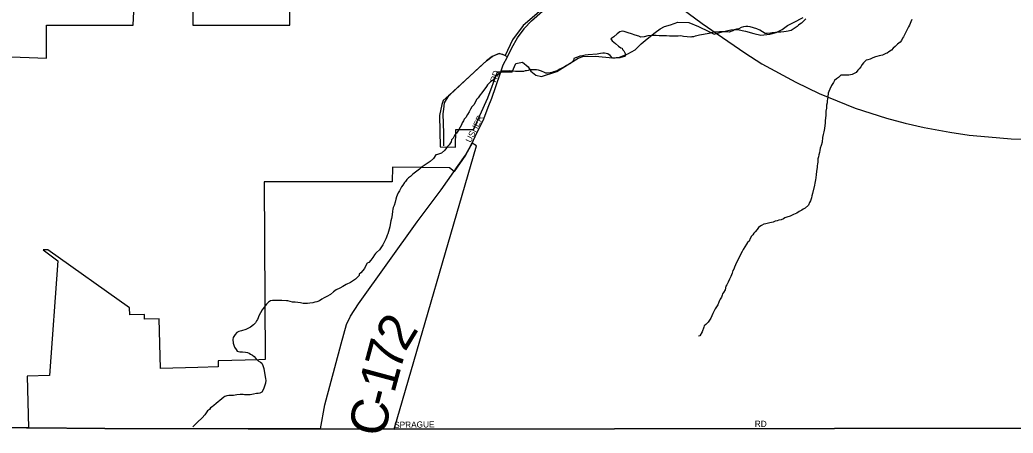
# Model space of a CAD drawing. Extents: x 2010165 to 2382125, y 1060529 to 1407316.
# Drawn here: x 2123534 to 2131582, y 1221198 to 1224542 of the extents above; entities that cross this region are included whole.
import ezdxf

# ---------------------------------------------------------------- set-up
doc = ezdxf.new("R2010")
doc.units = 0
for name, color, linetype in [('GM_X_Adjacent_County', 7, 'Continuous'), ('GM_X_City_Street', 7, 'Continuous'), ('GM_X_City_Street_Text', 7, 'Continuous'), ('GM_X_Corporation', 7, 'Continuous'), ('GM_X_County', 7, 'Continuous'), ('GM_X_County_Road', 7, 'Continuous'), ('GM_X_County_Road_Text', 7, 'Continuous'), ('GM_X_Interstate_Route', 7, 'Continuous'), ('GM_X_Minor_River', 7, 'Continuous'), ('GM_X_Township', 7, 'Continuous'), ('GM_X_Township_Road', 7, 'Continuous')]:
    doc.layers.add(name, color=color, linetype=linetype)

msp = doc.modelspace()

# ---------------------------------------------------------------- linework, layer by layer
at = {"layer": 'GM_X_Adjacent_County'}
msp.add_lwpolyline([(2113843.3, 1233474.2), (2113829.3, 1229946.4), (2113820.5, 1229023.2), (2113809.5, 1227825.9), (2113746.9, 1221286.8), (2114711.1, 1221285.7), (2116205.2, 1221283.5), (2117710.7, 1221282.1), (2118373.8, 1221279.2), (2120242, 1221263.8), (2121626.8, 1221258.9), (2123114.6, 1221244.8), (2123603.6, 1221240.6), (2124222.3, 1221236.2), (2125383.4, 1221233.3), (2125968.7, 1221233.7), (2126567.4, 1221231.3), (2131919.6, 1221238.9)], dxfattribs=at)
at = {"layer": 'GM_X_City_Street'}
for points in [[(2127190.5, 1223531.3), (2127198.2, 1223545.1), (2127222, 1223597.3), (2127293.2, 1223739.8), (2127328.8, 1223834.8), (2127357.4, 1223908.4), (2127425.5, 1224105.9)], [(2123111.3, 1221244.8), (2123114.6, 1221244.8), (2123587.4, 1221240.7)], [(2126558, 1221231.4), (2126567.4, 1221231.3), (2131919.6, 1221238.9)]]:
    msp.add_lwpolyline(points, dxfattribs=at)
at = {"layer": 'GM_X_Corporation'}
for points in [[(2123038.4, 1224258), (2123748.4, 1224233.1), (2123748.4, 1224498.2), (2124450.8, 1224498.1), (2124510.9, 1225707.3)], [(2124946.1, 1225396.8), (2124934, 1224498.7), (2125722.4, 1224498.6), (2125717.9, 1224762.7)], [(2127760.6, 1224622.5), (2127612.9, 1224495.2), (2127524.5, 1224379), (2127465.4, 1224253.9), (2127416.7, 1224269.3), (2127359.7, 1224245.6), (2127314.6, 1224210), (2127013, 1223932.1), (2126964.3, 1223888.5), (2126953.9, 1223857.3), (2126934.9, 1223767.2), (2126938.3, 1223514.3), (2127063.1, 1223512.6), (2127066.5, 1223654.6), (2127208.6, 1223654.6), (2127326.4, 1223911), (2127402.6, 1224122.3), (2127522.1, 1224122.3), (2127553.2, 1224189.1), (2127607.6, 1224199.3), (2127653.4, 1224161.8), (2127673.6, 1224127.8), (2127713.8, 1224094), (2127759.9, 1224082.3), (2127884.7, 1224124.4), (2128056.8, 1224230.7), (2128094.7, 1224245), (2128196.8, 1224249.1), (2128334.7, 1224234.7), (2128392.7, 1224241.1), (2128460.5, 1224267.7), (2128520.3, 1224300.1), (2128567.9, 1224348.6), (2128615.7, 1224387), (2128681.3, 1224439.6), (2128723.1, 1224467.9), (2128757, 1224488.2), (2128804.9, 1224502.6), (2128864.7, 1224523), (2128954.7, 1224521.7), (2129032.9, 1224488.1), (2129115.2, 1224446.6), (2129159.3, 1224426.9), (2129223.1, 1224445.4), (2129295, 1224461.9), (2129349, 1224464.3), (2129413, 1224450.7), (2129481.2, 1224431.2), (2129537.2, 1224417.5), (2129611.2, 1224426.1), (2129663.1, 1224438.5), (2129710.9, 1224462.8), (2129754.7, 1224497.2), (2129802.5, 1224521.6), (2129880.2, 1224562.2)], [(2131919.6, 1221238.9), (2126567.4, 1221231.3), (2127234.6, 1223521.2), (2127198.2, 1223545), (2127143.6, 1223447.7), (2127052.8, 1223315.8), (2127015.1, 1223344), (2126553.9, 1223349.5), (2126551.3, 1223232.1), (2125512.8, 1223231.1), (2125522.2, 1221793.6), (2125469.6, 1221791), (2125139.5, 1221782.4), (2125140.8, 1221734.4), (2124975.7, 1221730.1), (2124672, 1221721.1), (2124661.6, 1222122.2), (2124543.6, 1222119.2), (2124542.6, 1222157.2), (2124424.5, 1222154.1), (2124423, 1222212.8), (2123761.1, 1222681.9), (2123722.5, 1222681.9), (2123842.4, 1222591.5), (2123773.8, 1221664.2), (2123593.9, 1221660.1), (2123603.6, 1221240.6), (2123114.6, 1221244.8)]]:
    msp.add_lwpolyline(points, dxfattribs=at)
at = {"layer": 'GM_X_County'}
msp.add_lwpolyline([(2131919.6, 1221238.9), (2126567.4, 1221231.3), (2125968.7, 1221233.7), (2125383.4, 1221233.3), (2124222.3, 1221236.2), (2123603.6, 1221240.6), (2123114.6, 1221244.8), (2121626.8, 1221258.9), (2120242, 1221263.8), (2118373.8, 1221279.2), (2117710.7, 1221282.1), (2116205.2, 1221283.5), (2114711.1, 1221285.7), (2113746.9, 1221286.8), (2113809.5, 1227825.9), (2113820.5, 1229023.2), (2113829.3, 1229946.4), (2113843.3, 1233474.2)], dxfattribs=at)
at = {"layer": 'GM_X_County_Road'}
for points in [[(2127619.8, 1224469.6), (2127620.9, 1224471.2), (2127680.3, 1224533), (2127768.8, 1224613.5)], [(2127425.5, 1224105.9), (2127450, 1224176.7), (2127485.6, 1224243.2), (2127518.8, 1224316.8), (2127566.3, 1224397.6), (2127619.8, 1224469.6)], [(2127051.1, 1223313.3), (2127052.8, 1223315.9), (2127073, 1223344.7), (2127143.6, 1223447.7), (2127190.5, 1223531.3)], [(2125968.7, 1221233.7), (2126004.4, 1221426.8), (2126136.4, 1221920.3), (2126180.5, 1222077.5), (2126211.9, 1222143.5), (2126277.9, 1222244.1), (2126752.6, 1222907.5), (2126947.6, 1223165.3), (2127051.1, 1223313.3)], [(2123587.4, 1221240.7), (2123603.6, 1221240.6), (2124222.3, 1221236.2), (2125383.4, 1221233.3), (2125968.7, 1221233.7), (2126558, 1221231.4)]]:
    msp.add_lwpolyline(points, dxfattribs=at)
at = {"layer": 'GM_X_Interstate_Route'}
for points in [[(2123475.5, 1227509.9), (2124443.7, 1227272.2), (2124647.3, 1227222.4), (2124905.8, 1227162.1), (2125007.6, 1227137.2), (2125158.9, 1227094.4), (2125359.9, 1227026.5), (2125508.5, 1226969), (2125701.3, 1226886.4), (2125888.7, 1226792.8), (2126026.5, 1226713.5), (2126161.6, 1226630.5), (2126338.1, 1226511.3), (2126677.5, 1226265.6), (2127019.7, 1226012.5), (2127190.8, 1225889.7), (2127359.2, 1225763.1), (2127657.2, 1225546.3), (2127869.7, 1225387.2), (2128126.4, 1225203), (2128302.2, 1225075.8), (2128383, 1225015), (2129061.9, 1224512.7), (2129183.2, 1224428.9)], [(2129183.2, 1224428.9), (2129406.8, 1224274.3), (2129545.2, 1224186), (2129820.4, 1224036.4), (2130010.5, 1223946.5), (2130302.5, 1223828.1), (2130555.7, 1223745.8), (2130707.1, 1223706.7), (2130861.1, 1223671.3), (2131070.1, 1223632.6), (2131226.9, 1223608.1), (2131383.5, 1223594.5), (2131565, 1223580), (2131751.7, 1223575), (2132122, 1223568.4)]]:
    msp.add_lwpolyline(points, dxfattribs=at)
at = {"layer": 'GM_X_Minor_River'}
for points in [[(2129901.8, 1224550.6), (2129882, 1224530.2), (2129868.2, 1224516), (2129854.3, 1224505.8), (2129842.4, 1224499.6), (2129832.5, 1224489.4), (2129808.7, 1224471), (2129782.8, 1224456.5), (2129768.8, 1224454.3), (2129758.9, 1224450.2), (2129742.9, 1224447.9), (2129722.8, 1224445.6), (2129700.8, 1224443.3), (2129682.8, 1224443.1), (2129630.7, 1224436.3), (2129614.7, 1224434), (2129588.7, 1224431.6), (2129572.7, 1224431.4), (2129552.4, 1224445.2), (2129530.1, 1224458.9), (2129503.9, 1224470.5), (2129477.7, 1224478.2), (2129451.5, 1224485.8), (2129431.5, 1224487.5), (2129417.4, 1224487.3), (2129397.4, 1224485), (2129379.5, 1224478.8), (2129359.5, 1224470.4), (2129339.5, 1224466.1), (2129323.6, 1224459.9), (2129311.6, 1224453.7), (2129295.7, 1224447.4), (2129283.7, 1224443.2), (2129245.6, 1224444.7), (2129203.5, 1224446.1), (2129157.4, 1224441.4), (2129115.4, 1224432.8), (2129073.4, 1224424.1), (2129041.5, 1224417.6), (2129019.5, 1224411.3), (2129005.5, 1224409.1), (2128991.5, 1224404.9), (2128979.5, 1224404.7), (2128969.5, 1224402.5), (2128939.4, 1224404.1), (2128911.3, 1224407.7), (2128889.2, 1224411.4), (2128869.1, 1224411.1), (2128849.1, 1224410.8), (2128825, 1224410.5), (2128798.9, 1224410.1), (2128772.8, 1224411.7), (2128744.8, 1224411.3), (2128714.7, 1224412.9), (2128688.6, 1224414.5), (2128664.5, 1224414.1), (2128622.5, 1224411.5), (2128592.5, 1224405.1), (2128566.4, 1224402.7), (2128548.3, 1224410.4), (2128520.1, 1224418.1), (2128489.9, 1224427.7), (2128461.7, 1224437.3), (2128429.4, 1224448.9), (2128415.3, 1224450.6), (2128395.4, 1224444.3), (2128373.5, 1224430), (2128345.8, 1224405.5), (2128322, 1224389.1), (2128332.3, 1224373.2), (2128358.7, 1224349.5), (2128385, 1224329.8), (2128403.3, 1224316), (2128413.4, 1224312.2), (2128417.5, 1224302.2), (2128427.7, 1224292.3), (2128431.9, 1224280.3), (2128438, 1224268.4), (2128442.2, 1224256.4), (2128432.4, 1224244.2), (2128396.4, 1224233.6), (2128356.4, 1224231.1), (2128336.3, 1224232.8), (2128317.9, 1224254.6), (2128297.7, 1224266.3), (2128283.6, 1224270.1), (2128271.6, 1224272), (2128257.5, 1224271.8), (2128237.5, 1224269.5), (2128211.5, 1224265.1), (2128139.4, 1224260), (2128113.4, 1224255.6)], [(2130760.1, 1224545), (2130754.3, 1224526.9), (2130748.5, 1224512.8), (2130742.7, 1224498.6), (2130734.9, 1224484.5), (2130727.1, 1224468.3), (2130693.9, 1224405.6), (2130686.1, 1224393.5), (2130676.3, 1224375.3), (2130666.5, 1224361.1), (2130654.6, 1224352.9), (2130644.7, 1224344.7), (2130626.9, 1224326.4), (2130611.1, 1224314.1), (2130597.3, 1224297.8), (2130575.4, 1224283.5), (2130561.5, 1224271.2), (2130551.6, 1224269.1), (2130523.7, 1224256.6), (2130495.7, 1224250.2), (2130477.7, 1224245.9), (2130465.7, 1224241.8), (2130445.8, 1224235.4), (2130423.9, 1224225.1), (2130405.9, 1224218.8), (2130391.9, 1224214.6), (2130370.2, 1224194.2), (2130358.3, 1224180), (2130346.6, 1224161.8), (2130334.8, 1224145.5), (2130324.9, 1224135.3), (2130311.2, 1224115.1), (2130277.3, 1224100.5), (2130251.3, 1224094.1), (2130219.2, 1224093.7), (2130201.2, 1224095.4), (2130185.1, 1224093.2), (2130167.4, 1224074.8), (2130149.5, 1224064.6), (2130135.6, 1224052.3), (2130125.8, 1224036.1), (2130110.1, 1224011.8), (2130096.5, 1223981.5), (2130088.8, 1223961.3), (2130083, 1223949.2), (2130079.4, 1223919.1), (2130077.6, 1223903), (2130075.9, 1223886.9), (2130074.1, 1223870.8), (2130070.4, 1223850.7), (2130068.7, 1223828.6), (2130065, 1223802.5), (2130063.5, 1223770.3), (2130061.9, 1223746.2), (2130060.1, 1223728.1), (2130058.4, 1223706), (2130056.7, 1223685.9), (2130053, 1223663.8), (2130047.4, 1223635.6), (2130041.7, 1223613.5), (2130038.1, 1223589.3), (2130034.6, 1223553.2), (2130027, 1223525), (2130019.2, 1223504.8), (2130015.5, 1223484.7), (2130011.7, 1223468.6), (2130008, 1223450.4), (2130004.2, 1223434.3), (2130000.4, 1223418.2), (2130000.6, 1223404.2), (2129998.8, 1223394.1), (2129997.1, 1223374), (2129995.2, 1223364)], [(2128113.4, 1224255.6), (2128091.4, 1224251.3), (2128071.4, 1224247), (2128053.4, 1224240.7), (2128035.5, 1224234.4), (2128023.5, 1224230.2), (2128019.7, 1224214.1), (2127994.1, 1224187.6), (2127962.2, 1224173.1), (2127946.3, 1224160.9), (2127926.4, 1224150.5), (2127908.5, 1224142.2), (2127896.6, 1224136.1), (2127884.6, 1224129.9), (2127868.7, 1224123.6), (2127856.7, 1224121.4), (2127844.7, 1224117.2), (2127830.7, 1224113), (2127808.7, 1224110.7), (2127796.7, 1224110.5), (2127784.5, 1224116.4), (2127760.3, 1224128), (2127736.2, 1224133.7), (2127720.1, 1224137.5), (2127680, 1224136.9), (2127663.9, 1224136.7), (2127652, 1224132.5), (2127640, 1224130.3), (2127628, 1224128.1), (2127614, 1224123.9), (2127589.9, 1224123.6), (2127549.8, 1224125), (2127499.6, 1224128.2), (2127463.5, 1224127.7), (2127443.5, 1224125.4), (2127423.7, 1224107.1), (2127399.8, 1224094.7), (2127389.9, 1224090.5), (2127370.3, 1224056.1), (2127346.5, 1224039.7), (2127334.7, 1224027.5), (2127322.8, 1224017.3), (2127315, 1224003.1), (2127277.6, 1223952.4), (2127263.8, 1223936.2), (2127248.1, 1223911.9), (2127234.3, 1223897.6), (2127226.5, 1223879.4), (2127212.8, 1223855.2), (2127195, 1223836.8), (2127185.3, 1223818.6), (2127173.6, 1223796.4), (2127159.8, 1223776.1), (2127146.2, 1223751.8), (2127134.3, 1223739.6), (2127128.5, 1223723.5), (2127118.7, 1223709.3), (2127110.9, 1223693.1), (2127101.2, 1223672.9), (2127087.5, 1223648.6), (2127071.8, 1223624.3), (2127058, 1223612.1), (2127052.1, 1223602), (2127044.3, 1223583.8), (2127032.5, 1223571.6), (2127028.7, 1223555.5), (2127013, 1223531.2), (2126999.2, 1223516.9), (2126977.6, 1223486.5), (2126949.8, 1223464), (2126917.9, 1223451.5), (2126903.9, 1223449.3), (2126884.3, 1223418.9), (2126858.6, 1223394.5), (2126834.7, 1223380.1), (2126818.8, 1223369.8), (2126801, 1223357.5), (2126785.1, 1223347.2), (2126771.2, 1223335), (2126717.7, 1223294.1), (2126697.9, 1223275.7), (2126682, 1223263.5), (2126670.2, 1223249.2), (2126658.4, 1223235), (2126650.5, 1223224.9), (2126636.8, 1223204.6), (2126624.9, 1223190.4), (2126617.1, 1223174.2), (2126609.4, 1223158), (2126599.6, 1223141.8), (2126591.8, 1223123.7), (2126586, 1223109.5), (2126580.2, 1223091.4), (2126574.6, 1223067.2), (2126566.9, 1223041), (2126559.2, 1223022.9), (2126555.4, 1223010.8), (2126553.6, 1222994.7), (2126550, 1222964.5), (2126544.4, 1222934.3), (2126540.7, 1222916.2)], [(2129995.2, 1223364), (2129993.5, 1223345.9), (2129991.6, 1223333.8), (2129987.9, 1223315.7), (2129986.3, 1223289.6), (2129982.6, 1223263.4), (2129980.9, 1223247.4), (2129977.1, 1223233.3), (2129975.3, 1223219.2), (2129973.5, 1223203.1), (2129956.4, 1223136.6), (2129950.7, 1223118.5), (2129946.9, 1223102.4), (2129939.2, 1223078.2), (2129931.4, 1223064), (2129923.7, 1223041.8), (2129895.9, 1223019.4), (2129880, 1223011.1), (2129870.1, 1223002.9), (2129858.2, 1222996.7), (2129848.2, 1222990.6), (2129830.4, 1222978.3), (2129802.5, 1222965.8), (2129776.6, 1222953.4), (2129748.6, 1222945), (2129732.7, 1222940.7), (2129720.7, 1222932.5), (2129702.8, 1222924.2), (2129682.8, 1222919.9), (2129668.9, 1222915.7), (2129654.9, 1222913.5), (2129638.9, 1222905.2), (2129611, 1222898.8), (2129579, 1222892.3), (2129561, 1222888.1), (2129543.1, 1222877.8), (2129529.2, 1222869.5), (2129519.3, 1222861.4), (2129507.5, 1222845.1), (2129491.7, 1222826.8), (2129479.8, 1222816.6), (2129472, 1222802.5), (2129462.1, 1222790.3), (2129450.4, 1222772.1), (2129442.6, 1222751.9), (2129430.8, 1222739.7), (2129420.9, 1222727.5), (2129395.5, 1222685), (2129385.7, 1222668.8), (2129374, 1222644.5), (2129360.4, 1222614.2), (2129340.9, 1222579.8), (2129331.1, 1222559.6), (2129325.4, 1222541.5), (2129317.6, 1222525.3), (2129311.8, 1222513.2), (2129306.1, 1222491), (2129294.4, 1222464.8), (2129282.7, 1222442.5), (2129273, 1222420.3), (2129263.3, 1222398.1), (2129253.4, 1222385.9), (2129247.8, 1222357.7), (2129234.1, 1222335.4), (2129228.3, 1222325.3), (2129224.4, 1222313.2), (2129218.6, 1222297.1), (2129208.9, 1222280.9), (2129203, 1222270.8), (2129197.1, 1222258.7), (2129189.4, 1222236.5), (2129177.7, 1222220.2), (2129167.9, 1222204.1), (2129160.1, 1222187.9), (2129154.2, 1222175.8), (2129148.4, 1222165.6), (2129132.9, 1222127.3), (2129111.3, 1222096.9), (2129091.5, 1222076.5), (2129079.6, 1222066.3), (2129075.8, 1222056.2), (2129062.3, 1222017.9), (2129044.7, 1221985.5), (2129032.7, 1221981.3), (2129032.7, 1221981.3)], [(2126540.7, 1222916.2), (2126536.9, 1222902.1), (2126531.4, 1222865.9), (2126521.9, 1222829.7), (2126514.2, 1222809.5), (2126510.3, 1222799.4), (2126504.5, 1222783.3), (2126498.7, 1222771.1), (2126490.9, 1222755), (2126475.3, 1222720.6), (2126447.9, 1222680.1), (2126424.1, 1222659.7), (2126414.2, 1222651.5), (2126406.3, 1222639.3), (2126394.6, 1222619.1), (2126378.9, 1222596.8), (2126361.1, 1222578.5), (2126347.2, 1222572.3), (2126335.5, 1222548), (2126325.7, 1222529.8), (2126296.1, 1222495.3), (2126282.3, 1222485), (2126282.4, 1222473), (2126252.8, 1222442.4), (2126213.1, 1222417.8), (2126177.2, 1222399.2), (2126149.4, 1222384.8), (2126127.5, 1222370.4), (2126097.6, 1222357.9), (2126075.8, 1222341.5), (2126050.1, 1222319.1), (2126022.2, 1222302.6), (2126000.3, 1222292.3), (2125980.4, 1222281.9), (2125960.5, 1222269.6), (2125940.6, 1222261.3), (2125924.6, 1222257.1), (2125906.6, 1222252.8), (2125882.6, 1222248.4), (2125864.6, 1222246.1), (2125844.6, 1222245.8), (2125828.5, 1222247.6), (2125808.4, 1222251.3), (2125786.3, 1222255), (2125764.2, 1222256.7), (2125744.1, 1222258.4), (2125724, 1222264.2), (2125705.9, 1222267.9), (2125693.8, 1222269.7), (2125655.7, 1222271.2), (2125615.6, 1222270.6), (2125581.5, 1222270.1), (2125563.5, 1222267.8), (2125547.6, 1222257.6), (2125531.8, 1222241.3), (2125512.1, 1222216.9), (2125504.3, 1222206.8), (2125496.4, 1222196.6), (2125471.1, 1222146.1), (2125465.2, 1222131.9), (2125459.4, 1222117.8), (2125451.6, 1222105.6), (2125443.8, 1222091.5), (2125428, 1222073.2), (2125402.2, 1222054.8), (2125364.4, 1222036.2), (2125330.4, 1222025.6), (2125308.5, 1222019.3), (2125292.5, 1222011), (2125278.7, 1221996.8), (2125263, 1221972.5), (2125259.3, 1221954.3), (2125261.7, 1221926.3), (2125272.2, 1221894.3), (2125286.5, 1221874.5), (2125294.7, 1221860.6), (2125316.8, 1221856.9), (2125338.9, 1221855.2), (2125361, 1221853.5), (2125377.1, 1221849.7), (2125391.2, 1221843.9), (2125403.3, 1221838.1), (2125417.5, 1221828.2), (2125431.7, 1221818.4), (2125446, 1221800.6), (2125464.3, 1221782.8), (2125482.5, 1221771), (2125494.7, 1221763.1), (2125502.9, 1221745.2), (2125511.3, 1221721.2), (2125515.8, 1221685.2), (2125520.3, 1221655.1), (2125524.6, 1221637.2), (2125526.7, 1221627.1), (2125525.1, 1221603), (2125507.7, 1221554.6), (2125494, 1221530.3), (2125478.1, 1221522.1), (2125464.1, 1221519.9), (2125450.1, 1221517.7), (2125428.1, 1221513.3)], [(2125428.1, 1221513.3), (2125400.1, 1221508.9), (2125378, 1221508.6), (2125354, 1221508.2), (2125341.9, 1221510.1), (2125319.8, 1221511.8), (2125291.8, 1221507.3), (2125263.8, 1221502.9), (2125243.8, 1221502.6), (2125227.7, 1221502.4), (2125211.7, 1221500.1), (2125195.8, 1221493.9), (2125185.8, 1221489.7), (2125170, 1221475.4), (2125154.1, 1221463.2), (2125140.3, 1221450.9), (2125124.4, 1221438.6), (2125106.6, 1221422.3), (2125090.7, 1221410.1), (2125078.8, 1221401.9), (2125069, 1221389.7), (2125055.1, 1221377.4), (2125043.3, 1221363.2), (2125031.5, 1221345), (2125009.8, 1221322.6), (2124974.2, 1221285.9), (2124936.6, 1221249.9)]]:
    msp.add_lwpolyline(points, dxfattribs=at)
at = {"layer": 'GM_X_Township'}
msp.add_lwpolyline([(2131919.6, 1221238.9), (2126567.4, 1221231.3), (2125968.7, 1221233.7), (2125383.4, 1221233.3), (2124222.3, 1221236.2), (2123603.6, 1221240.6), (2123114.6, 1221244.8), (2121626.8, 1221258.9), (2120242, 1221263.8), (2118373.8, 1221279.2), (2117710.7, 1221282.1), (2116205.2, 1221283.5), (2114711.1, 1221285.7), (2113746.9, 1221286.8), (2113809.5, 1227825.9), (2113820.5, 1229023.2), (2113829.3, 1229946.4), (2113843.3, 1233474.2)], dxfattribs=at)
at = {"layer": 'GM_X_Township_Road'}
for points in [[(2127258.5, 1224158.3), (2127314.6, 1224210), (2127359.7, 1224245.6), (2127383.5, 1224257.5), (2127416.7, 1224269.3), (2127445.2, 1224264.6), (2127465.4, 1224253.9), (2127485.6, 1224243.2)], [(2127020.2, 1223938.7), (2127258.5, 1224158.3)], [(2126967.9, 1223521.3), (2126967.9, 1223625.8), (2126963.1, 1223780.2), (2126967.9, 1223820.5), (2126975, 1223870.4), (2127013, 1223932.1), (2127020.2, 1223938.7)]]:
    msp.add_lwpolyline(points, dxfattribs=at)

# ---------------------------------------------------------------- texts
at = {"layer": 'GM_X_City_Street_Text'}
for s, rotation, p in [('RD', 71.5614, (2127389.8, 1224031.4)), ('USHER', 63.99633, (2127187.9, 1223544.1)), ('SPRAGUE', 0.89469, (2126567, 1221239.4)), ('RD', 0.00001, (2129488.7, 1221248.2))]:
    msp.add_text(s, height=50, rotation=rotation, dxfattribs=at).set_placement(p)
at = {"layer": 'GM_X_County_Road_Text'}
for s, rotation, p in [('2', 58.68415, (2126654.2, 1221849.3)), ('7', 74.89594, (2126614.9, 1221691.4)), ('1', 74.90599, (2126566.7, 1221513)), ('C', 78.25415, (2126486.4, 1221157.1)), ('-', 75.30113, (2126535.6, 1221394.3))]:
    msp.add_text(s, height=300, rotation=rotation, dxfattribs=at).set_placement(p)

doc.saveas('drawing.dxf')
